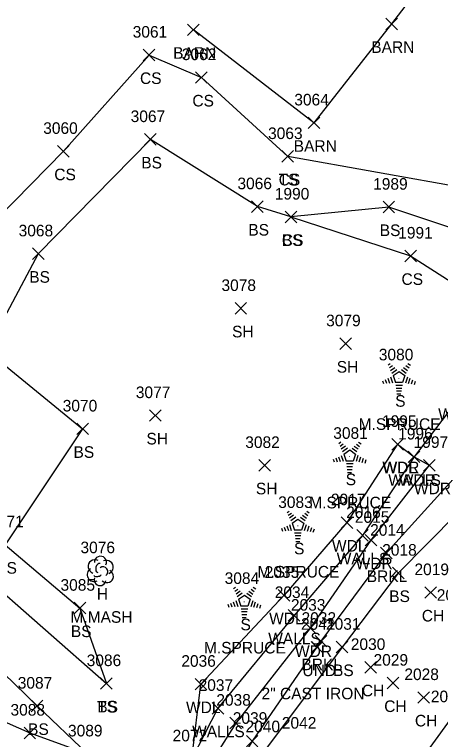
# Model space of a CAD drawing. Extents: x 1499292 to 1501024, y 534584 to 538043.
# Drawn here: x 1499814.4 to 1499887.8, y 537733.8 to 537858.9 of the extents above; entities that cross this region are included whole.
import ezdxf

# ---------------------------------------------------------------- set-up
doc = ezdxf.new("R2010")
doc.units = 0
for name, color, linetype in [('D_A', 7, 'Continuous'), ('D_C', 7, 'Continuous'), ('D_I', 7, 'Continuous'), ('D_TIC', 7, 'Continuous'), ('L_A', 7, 'Continuous'), ('L_C', 7, 'Continuous'), ('L_I', 7, 'Continuous'), ('L_TIC', 7, 'Continuous'), ('LAPB', 7, 'Continuous'), ('LAWA', 7, 'Continuous'), ('LAWE', 7, 'Continuous'), ('LBC', 7, 'Continuous'), ('LELB', 7, 'Continuous'), ('LTC', 7, 'Continuous'), ('LTD', 7, 'Continuous'), ('LWS', 7, 'Continuous')]:
    doc.layers.add(name, color=color, linetype=linetype)

msp = doc.modelspace()

# ---------------------------------------------------------------- linework, layer by layer
at = {"layer": 'D_TIC'}
for points in [[(1499865.55, 537748.77), (1499867.55, 537750.77)], [(1499867.55, 537748.77), (1499865.55, 537750.77)]]:
    msp.add_lwpolyline(points, dxfattribs=at)
at = {"layer": 'L_TIC'}
for points in [[(1499878.39, 537856.32), (1499880.39, 537858.32)], [(1499880.39, 537856.32), (1499878.39, 537858.32)], [(1499844.24, 537855.3), (1499846.24, 537857.3)], [(1499846.24, 537855.3), (1499844.24, 537857.3)], [(1499836.6, 537850.95), (1499838.6, 537852.95)], [(1499838.6, 537850.95), (1499836.6, 537852.95)], [(1499845.63, 537847.07), (1499847.63, 537849.07)], [(1499847.63, 537847.07), (1499845.63, 537849.07)], [(1499865.02, 537839.25), (1499867.02, 537841.25)], [(1499867.02, 537839.25), (1499865.02, 537841.25)], [(1499836.82, 537836.38), (1499838.82, 537838.38)], [(1499838.82, 537836.38), (1499836.82, 537838.38)], [(1499821.83, 537834.34), (1499823.83, 537836.34)], [(1499823.83, 537834.34), (1499821.83, 537836.34)], [(1499860.5, 537833.45), (1499862.5, 537835.45)], [(1499862.5, 537833.45), (1499860.5, 537835.45)], [(1499860.5, 537833.45), (1499862.5, 537835.45)], [(1499862.5, 537833.45), (1499860.5, 537835.45)], [(1499855.27, 537824.79), (1499857.27, 537826.79)], [(1499857.27, 537824.79), (1499855.27, 537826.79)], [(1499877.92, 537824.71), (1499879.92, 537826.71)], [(1499879.92, 537824.71), (1499877.92, 537826.71)], [(1499861.05, 537823.01), (1499863.05, 537825.01)], [(1499863.05, 537823.01), (1499861.05, 537825.01)], [(1499861.05, 537823.01), (1499863.05, 537825.01)], [(1499863.05, 537823.01), (1499861.05, 537825.01)], [(1499817.51, 537816.66), (1499819.51, 537818.66)], [(1499819.51, 537816.66), (1499817.51, 537818.66)], [(1499881.67, 537816.28), (1499883.67, 537818.28)], [(1499883.67, 537816.28), (1499881.67, 537818.28)], [(1499852.42, 537807.23), (1499854.42, 537809.23)], [(1499854.42, 537807.23), (1499852.42, 537809.23)], [(1499870.47, 537801.14), (1499872.47, 537803.14)], [(1499872.47, 537801.14), (1499870.47, 537803.14)], [(1499837.66, 537788.75), (1499839.66, 537790.75)], [(1499839.66, 537788.75), (1499837.66, 537790.75)], [(1499825.14, 537786.44), (1499827.14, 537788.44)], [(1499827.14, 537786.44), (1499825.14, 537788.44)], [(1499879.44, 537783.78), (1499881.44, 537785.78)], [(1499881.44, 537783.78), (1499879.44, 537785.78)], [(1499879.44, 537783.78), (1499881.44, 537785.78)], [(1499881.44, 537783.78), (1499879.44, 537785.78)], [(1499882.28, 537781.61), (1499884.28, 537783.61)], [(1499884.28, 537781.61), (1499882.28, 537783.61)], [(1499882.28, 537781.61), (1499884.28, 537783.61)], [(1499884.28, 537781.61), (1499882.28, 537783.61)], [(1499856.52, 537780.14), (1499858.52, 537782.14)], [(1499858.52, 537780.14), (1499856.52, 537782.14)], [(1499884.89, 537780.16), (1499886.89, 537782.16)], [(1499886.89, 537780.16), (1499884.89, 537782.16)], [(1499870.7, 537770.26), (1499872.7, 537772.26)], [(1499872.7, 537770.26), (1499870.7, 537772.26)], [(1499873.39, 537768.05), (1499875.39, 537770.05)], [(1499875.39, 537768.05), (1499873.39, 537770.05)], [(1499874.84, 537767.23), (1499876.84, 537769.23)], [(1499876.84, 537767.23), (1499874.84, 537769.23)], [(1499877.48, 537765), (1499879.48, 537767)], [(1499879.48, 537765), (1499877.48, 537767)], [(1499879.55, 537761.56), (1499881.55, 537763.56)], [(1499881.55, 537761.56), (1499879.55, 537763.56)], [(1499859.87, 537757.73), (1499861.87, 537759.73)], [(1499861.87, 537757.73), (1499859.87, 537759.73)], [(1499885.12, 537758.2), (1499887.12, 537760.2)], [(1499887.12, 537758.2), (1499885.12, 537760.2)], [(1499824.68, 537755.51), (1499826.68, 537757.51)], [(1499826.68, 537755.51), (1499824.68, 537757.51)], [(1499861.6, 537754.25), (1499863.6, 537756.25)], [(1499863.6, 537754.25), (1499861.6, 537756.25)], [(1499864.39, 537752.07), (1499866.39, 537754.07)], [(1499866.39, 537752.07), (1499864.39, 537754.07)], [(1499866.22, 537749.8), (1499868.22, 537751.8)], [(1499868.22, 537749.8), (1499866.22, 537751.8)], [(1499869.86, 537748.78), (1499871.86, 537750.78)], [(1499871.86, 537748.78), (1499869.86, 537750.78)], [(1499874.79, 537745.29), (1499876.79, 537747.29)], [(1499876.79, 537745.29), (1499874.79, 537747.29)], [(1499829.24, 537742.5), (1499831.24, 537744.5)], [(1499831.24, 537742.5), (1499829.24, 537744.5)], [(1499829.24, 537742.5), (1499831.24, 537744.5)], [(1499831.24, 537742.5), (1499829.24, 537744.5)], [(1499845.55, 537742.39), (1499847.55, 537744.39)], [(1499847.55, 537742.39), (1499845.55, 537744.39)], [(1499878.64, 537742.58), (1499880.64, 537744.58)], [(1499880.64, 537742.58), (1499878.64, 537744.58)], [(1499883.94, 537740.09), (1499885.94, 537742.09)], [(1499885.94, 537740.09), (1499883.94, 537742.09)], [(1499817.31, 537738.62), (1499819.31, 537740.62)], [(1499819.31, 537738.62), (1499817.31, 537740.62)], [(1499848.48, 537738.23), (1499850.48, 537740.23)], [(1499850.48, 537738.23), (1499848.48, 537740.23)], [(1499851.53, 537735.67), (1499853.53, 537737.67)], [(1499853.53, 537735.67), (1499851.53, 537737.67)], [(1499816.05, 537733.96), (1499818.05, 537735.96)], [(1499818.05, 537733.96), (1499816.05, 537735.96)], [(1499854.37, 537732.55), (1499856.37, 537734.55)], [(1499856.37, 537732.55), (1499854.37, 537734.55)]]:
    msp.add_lwpolyline(points, dxfattribs=at)
at = {"layer": 'LAPB'}
msp.add_lwpolyline([(1499801.41, 537738.15), (1499803.85, 537740.8), (1499817.05, 537734.96), (1499826.98, 537731.37), (1499832.07, 537725.79), (1499830.07, 537721.19), (1499824.29, 537718.43), (1499822.44, 537716.53)], dxfattribs=at)
at = {"layer": 'LAWA'}
for points in [[(1499880.44, 537784.78), (1499883.28, 537782.61), (1499885.89, 537781.16), (1499875.84, 537768.23), (1499865.39, 537753.07), (1499852.53, 537736.67), (1499844.57, 537724.02), (1499844.99, 537730.52)], [(1499880.44, 537784.78), (1499871.7, 537771.26), (1499860.87, 537758.73), (1499846.55, 537743.39)], [(1499844.99, 537730.52), (1499846.55, 537743.39)]]:
    msp.add_lwpolyline(points, dxfattribs=at)
at = {"layer": 'LAWE'}
msp.add_lwpolyline([(1499929.73, 537843.16), (1499921.15, 537828.37), (1499911.21, 537810.95), (1499902.71, 537799.07), (1499891.7, 537780.61), (1499878.48, 537766), (1499867.22, 537750.8), (1499855.37, 537733.55), (1499847.56, 537720.49), (1499833.23, 537714.68)], dxfattribs=at)
at = {"layer": 'LBC'}
msp.add_lwpolyline([(1499890.83, 537872.27), (1499879.39, 537857.32), (1499866.02, 537840.25), (1499845.24, 537856.3)], dxfattribs=at)
at = {"layer": 'LELB'}
for points in [[(1499799.26, 537773.33), (1499808.36, 537785), (1499799.96, 537794.9), (1499801.41, 537807.8), (1499808.78, 537821.02), (1499822.83, 537835.34), (1499837.6, 537851.95), (1499846.63, 537848.07), (1499861.5, 537834.45)], [(1499931.33, 537841.3), (1499922.8, 537827.37), (1499912.72, 537807.85), (1499905.96, 537796.12), (1499895.82, 537778.01), (1499880.55, 537762.56), (1499870.86, 537749.78), (1499857.65, 537732.09), (1499849.89, 537720.06), (1499839.9, 537710.15), (1499830.87, 537699.25), (1499819.75, 537691.27), (1499813.25, 537682.44), (1499807.24, 537678.73), (1499801.4, 537680.95), (1499789.92, 537664.22), (1499779.13, 537655.09), (1499771.86, 537652.25), (1499758.58, 537645.46), (1499745.45, 537639.29), (1499734.4, 537633.25), (1499715.96, 537632.7), (1499700.46, 537632.22)], [(1499911.08, 537815.73), (1499889.77, 537822.06), (1499878.92, 537825.71), (1499862.05, 537824.01), (1499856.27, 537825.79), (1499837.82, 537837.38), (1499818.51, 537817.66), (1499809.61, 537800.99), (1499826.14, 537787.44), (1499812.81, 537767.45), (1499825.68, 537756.51), (1499830.24, 537743.5)], [(1499908.06, 537822.08), (1499892.45, 537828.9), (1499861.5, 537834.45)], [(1499862.05, 537824.01), (1499882.67, 537817.28), (1499898.74, 537807.01)], [(1499958.72, 537820.12), (1499949.1, 537803.7), (1499937.21, 537786.88), (1499926.5, 537779.14), (1499915.43, 537766.61), (1499901.39, 537746.71), (1499889.51, 537737.27), (1499877.77, 537721.1), (1499874.08, 537712.66), (1499871.12, 537712.1), (1499865.76, 537707.44), (1499861.54, 537702.35), (1499859.64, 537699.06)], [(1499799.26, 537773.33), (1499808.24, 537762.8), (1499830.24, 537743.5)], [(1499782.83, 537767.39), (1499804.79, 537752.68), (1499818.31, 537739.62), (1499826.98, 537731.37)]]:
    msp.add_lwpolyline(points, dxfattribs=at)
at = {"layer": 'LTC'}
for p, q in [((1499878.82, 537798.47), (1499879.18, 537798.73)), ((1499879.03, 537798.01), (1499879.56, 537798.39)), ((1499881.85, 537798.36), (1499882.4, 537797.97)), ((1499882.22, 537798.71), (1499882.64, 537798.41)), ((1499879.24, 537797.54), (1499879.95, 537798.05)), ((1499879.45, 537797.08), (1499880.33, 537797.71)), ((1499879.68, 537796.62), (1499880.69, 537797.36)), ((1499880.69, 537797.36), (1499881.69, 537796.63)), ((1499881.11, 537797.67), (1499881.92, 537797.08)), ((1499881.48, 537798.02), (1499882.16, 537797.52)), ((1499877.86, 537795.75), (1499878.01, 537795.28)), ((1499878.31, 537795.97), (1499878.52, 537795.32)), ((1499878.77, 537796.19), (1499879.04, 537795.35)), ((1499879.22, 537796.4), (1499879.55, 537795.38)), ((1499879.68, 537796.62), (1499880.07, 537795.43)), ((1499881.69, 537796.63), (1499881.3, 537795.43)), ((1499882.12, 537796.36), (1499881.79, 537795.32)), ((1499882.57, 537796.11), (1499882.28, 537795.22)), ((1499883.01, 537795.86), (1499882.78, 537795.13)), ((1499881.3, 537795.43), (1499880.07, 537795.43)), ((1499881.26, 537794.93), (1499880.11, 537794.93)), ((1499881.17, 537794.43), (1499880.19, 537794.43)), ((1499883.46, 537795.61), (1499883.27, 537795.03)), ((1499881.09, 537793.93), (1499880.26, 537793.93)), ((1499881.01, 537793.43), (1499880.33, 537793.43)), ((1499870.31, 537784.93), (1499870.67, 537785.19)), ((1499870.52, 537784.46), (1499871.05, 537784.85)), ((1499870.73, 537784), (1499871.44, 537784.51)), ((1499872.97, 537784.47), (1499873.65, 537783.98)), ((1499873.34, 537784.82), (1499873.89, 537784.42)), ((1499873.71, 537785.17), (1499874.13, 537784.87)), ((1499870.94, 537783.53), (1499871.82, 537784.17)), ((1499871.17, 537783.08), (1499872.18, 537783.81)), ((1499872.18, 537783.81), (1499873.18, 537783.09)), ((1499872.6, 537784.12), (1499873.41, 537783.54)), ((1499869.35, 537782.21), (1499869.5, 537781.74)), ((1499869.8, 537782.43), (1499870.01, 537781.77)), ((1499870.26, 537782.64), (1499870.53, 537781.81)), ((1499870.71, 537782.86), (1499871.04, 537781.84)), ((1499871.17, 537783.08), (1499871.55, 537781.88)), ((1499872.78, 537781.88), (1499871.55, 537781.88)), ((1499873.18, 537783.09), (1499872.78, 537781.88)), ((1499873.61, 537782.82), (1499873.28, 537781.78)), ((1499874.06, 537782.57), (1499873.77, 537781.68)), ((1499874.5, 537782.32), (1499874.27, 537781.59)), ((1499874.95, 537782.07), (1499874.76, 537781.49)), ((1499872.75, 537781.38), (1499871.6, 537781.38)), ((1499872.66, 537780.88), (1499871.67, 537780.88)), ((1499872.58, 537780.38), (1499871.75, 537780.38)), ((1499872.5, 537779.88), (1499871.82, 537779.88)), ((1499861.4, 537773), (1499861.75, 537773.26)), ((1499864.79, 537773.24), (1499865.21, 537772.94)), ((1499861.6, 537772.54), (1499862.13, 537772.92)), ((1499861.81, 537772.07), (1499862.52, 537772.58)), ((1499862.02, 537771.6), (1499862.9, 537772.24)), ((1499862.25, 537771.15), (1499863.26, 537771.88)), ((1499863.26, 537771.88), (1499864.26, 537771.16)), ((1499863.68, 537772.2), (1499864.49, 537771.61)), ((1499864.05, 537772.55), (1499864.73, 537772.05)), ((1499864.42, 537772.89), (1499864.97, 537772.49)), ((1499861.34, 537770.71), (1499861.61, 537769.88)), ((1499861.79, 537770.93), (1499862.12, 537769.91)), ((1499862.25, 537771.15), (1499862.64, 537769.96)), ((1499864.26, 537771.16), (1499863.87, 537769.96)), ((1499864.69, 537770.89), (1499864.36, 537769.85)), ((1499865.14, 537770.64), (1499864.85, 537769.75)), ((1499860.43, 537770.28), (1499860.58, 537769.81)), ((1499860.88, 537770.5), (1499861.09, 537769.85)), ((1499863.87, 537769.96), (1499862.64, 537769.96)), ((1499863.83, 537769.46), (1499862.68, 537769.46)), ((1499865.58, 537770.39), (1499865.35, 537769.66)), ((1499866.03, 537770.14), (1499865.84, 537769.56)), ((1499863.74, 537768.96), (1499862.76, 537768.96)), ((1499863.66, 537768.46), (1499862.83, 537768.46)), ((1499863.58, 537767.96), (1499862.9, 537767.96)), ((1499852.17, 537759.89), (1499852.52, 537760.14)), ((1499852.38, 537759.42), (1499852.91, 537759.8)), ((1499852.59, 537758.95), (1499853.29, 537759.47)), ((1499854.82, 537759.43), (1499855.5, 537758.94)), ((1499855.19, 537759.78), (1499855.74, 537759.38)), ((1499855.56, 537760.13), (1499855.98, 537759.82)), ((1499852.8, 537758.49), (1499853.67, 537759.13)), ((1499853.02, 537758.03), (1499854.03, 537758.77)), ((1499854.03, 537758.77), (1499855.03, 537758.04)), ((1499854.45, 537759.08), (1499855.26, 537758.49)), ((1499851.2, 537757.17), (1499851.35, 537756.7)), ((1499851.65, 537757.38), (1499851.87, 537756.73)), ((1499852.11, 537757.6), (1499852.38, 537756.76)), ((1499852.57, 537757.81), (1499852.9, 537756.8)), ((1499853.02, 537758.03), (1499853.41, 537756.84)), ((1499855.03, 537758.04), (1499854.64, 537756.84)), ((1499855.47, 537757.77), (1499855.13, 537756.73)), ((1499855.91, 537757.52), (1499855.62, 537756.64)), ((1499856.36, 537757.27), (1499856.12, 537756.54)), ((1499856.8, 537757.02), (1499856.61, 537756.45)), ((1499854.64, 537756.84), (1499853.41, 537756.84)), ((1499854.6, 537756.34), (1499853.45, 537756.34)), ((1499854.52, 537755.84), (1499853.53, 537755.84)), ((1499854.43, 537755.34), (1499853.6, 537755.34)), ((1499854.35, 537754.84), (1499853.67, 537754.84))]:
    msp.add_line(p, q, dxfattribs=at)
at = {"layer": 'LTD'}
msp.add_line((1499829.17, 537762.98), (1499829.17, 537762.98), dxfattribs=at)
msp.add_line((1499829.17, 537762.98), (1499829.17, 537762.98), dxfattribs=at)
msp.add_arc((1499829.22, 537764.41), 1.05, 335.5272, 180.9563, dxfattribs=at)
for centre, major_axis, ratio, start_param, end_param in [((1499828.38, 537763.64), (1.21, -0.51), 0.895232, 1.570796, 4.712389), ((1499830.21, 537763.56), (-1.14, -0.48), 0.949671, 1.570796, 4.712389), ((1499828.09, 537762.27), (0.58, -1.04), 0.959034, 3.141593, 6.283185), ((1499828.96, 537763.43), (-0.208, -0.792), 0.645439, 3.141593, 6.283185), ((1499829.67, 537762.81), (-0.5, 0.667), 0.989748, 3.141593, 6.283185), ((1499828.71, 537762.23), (-0.625, -0.083), 0.423636, 0, 3.141593), ((1499830.17, 537762.14), (-1.09, 0.79), 0.841452, 1.570796, 4.712389), ((1499829.17, 537761.48), (0.26, 1.06), 0.942809, 1.570796, 4.712389)]:
    msp.add_ellipse(centre, major_axis=major_axis, ratio=ratio, start_param=start_param, end_param=end_param, dxfattribs=at)
at = {"layer": 'LWS'}
msp.add_lwpolyline([(1499897.8, 537803.79), (1499891.88, 537793.96), (1499883.28, 537782.61), (1499874.39, 537769.05), (1499862.6, 537755.25), (1499849.48, 537739.23), (1499844.99, 537730.52)], dxfattribs=at)

# ---------------------------------------------------------------- texts
at = {"layer": 'D_A'}
msp.add_text('UND', height=2, dxfattribs=at).set_placement((1499864.03, 537744.77))
at = {"layer": 'D_C'}
msp.add_text('2" CAST IRON', height=2, dxfattribs=at).set_placement((1499856.99, 537740.77))
at = {"layer": 'D_I'}
msp.add_text('2041', height=2, dxfattribs=at).set_placement((1499863.78, 537752.77))
at = {"layer": 'L_A'}
for s, p in [('BARN', (1499841.75, 537851.3)), ('BARN', (1499875.9, 537852.32)), ('CS', (1499836.04, 537846.95)), ('CS', (1499845.07, 537843.07)), ('BARN', (1499862.53, 537835.25)), ('BS', (1499836.26, 537832.38)), ('CS', (1499821.27, 537830.34)), ('TS', (1499859.91, 537829.45)), ('CS', (1499859.94, 537829.45)), ('BS', (1499854.71, 537820.79)), ('BS', (1499877.36, 537820.71)), ('CS', (1499860.49, 537819.01)), ('BS', (1499860.49, 537819.01)), ('BS', (1499816.95, 537812.66)), ('CS', (1499881.11, 537812.28)), ('SH', (1499851.91, 537803.23)), ('SH', (1499869.95, 537797.14)), ('S', (1499880.02, 537791.26)), ('WALLS', (1499887.43, 537788.96)), ('SH', (1499837.15, 537784.75)), ('BS', (1499824.58, 537782.44)), ('WDR', (1499877.8, 537779.78)), ('WDL', (1499877.86, 537779.78)), ('S', (1499871.5, 537777.72)), ('WALLS', (1499878.83, 537777.61)), ('WDR', (1499880.64, 537777.61)), ('SH', (1499856.01, 537776.14)), ('WDR', (1499883.25, 537776.16)), ('WDL', (1499869.12, 537766.26)), ('S', (1499862.59, 537765.79)), ('WALLS', (1499869.94, 537764.05)), ('BS', (1499811.26, 537762.45)), ('WDR', (1499873.2, 537763.23)), ('BRKL', (1499875.12, 537761)), ('H', (1499828.6, 537757.98)), ('BS', (1499878.99, 537757.56)), ('WDL', (1499858.29, 537753.73)), ('CH', (1499884.61, 537754.2)), ('S', (1499853.36, 537752.68)), ('BS', (1499824.12, 537751.51)), ('WALLS', (1499858.14, 537750.25)), ('WDR', (1499862.75, 537748.07)), ('BRKL', (1499863.87, 537745.8)), ('BS', (1499869.3, 537744.78)), ('CH', (1499874.28, 537741.29)), ('CH', (1499878.13, 537738.58)), ('TS', (1499828.65, 537738.5)), ('BS', (1499828.68, 537738.5)), ('WDL', (1499843.97, 537738.39)), ('CH', (1499883.42, 537736.09)), ('BS', (1499816.75, 537734.62)), ('WALLS', (1499845.02, 537734.23))]:
    msp.add_text(s, height=2, dxfattribs=at).set_placement(p)
at = {"layer": 'L_C'}
for s, p in [('M.SPRUCE', (1499873.72, 537787.26)), ('M.SPRUCE', (1499865.21, 537773.72)), ('M.SPRUCE', (1499856.29, 537761.79)), ('M.MASH', (1499824.05, 537753.98)), ('M.SPRUCE', (1499847.06, 537748.68))]:
    msp.add_text(s, height=2, dxfattribs=at).set_placement(p)
at = {"layer": 'L_I'}
for s, p in [('3061', (1499834.78, 537854.95)), ('3062', (1499843.24, 537851.07)), ('3064', (1499862.63, 537843.25)), ('3067', (1499834.43, 537840.38)), ('3060', (1499819.36, 537838.34)), ('3063', (1499858.11, 537837.45)), ('3063', (1499858.11, 537837.45)), ('3066', (1499852.83, 537828.79)), ('1989', (1499876.22, 537828.71)), ('1990', (1499859.27, 537827.01)), ('1990', (1499859.27, 537827.01)), ('3068', (1499815.12, 537820.66)), ('1991', (1499880.54, 537820.28)), ('3078', (1499850.08, 537811.23)), ('3079', (1499868.12, 537805.14)), ('3080', (1499877.2, 537799.26)), ('3077', (1499835.32, 537792.75)), ('3070', (1499822.72, 537790.44)), ('1995', (1499877.75, 537787.78)), ('1995', (1499877.75, 537787.78)), ('3081', (1499869.35, 537785.72)), ('1996', (1499880.53, 537785.61)), ('1996', (1499880.53, 537785.61)), ('3082', (1499854.18, 537784.14)), ('1997', (1499883.2, 537784.16)), ('3083', (1499859.86, 537773.79)), ('2017', (1499868.93, 537774.26)), ('2016', (1499871.57, 537772.05)), ('2015', (1499873.07, 537771.23)), ('3071', (1499810.04, 537770.45)), ('2014', (1499875.7, 537769)), ('3076', (1499825.78, 537765.98)), ('2018', (1499877.78, 537765.56)), ('2035', (1499857.53, 537761.73)), ('2019', (1499883.34, 537762.2)), ('3084', (1499850.63, 537760.68)), ('3085', (1499822.34, 537759.51)), ('2034', (1499859.26, 537758.25)), ('2020', (1499887.19, 537757.77)), ('2033', (1499862.05, 537756.07)), ('2032', (1499863.88, 537753.8)), ('2031', (1499868.09, 537752.78)), ('2030', (1499872.37, 537749.29)), ('3086', (1499826.85, 537746.5)), ('3086', (1499826.85, 537746.5)), ('2036', (1499843.16, 537746.39)), ('2029', (1499876.29, 537746.58)), ('2028', (1499881.6, 537744.09)), ('3087', (1499814.97, 537742.62)), ('2037', (1499846.14, 537742.23)), ('2027', (1499886.17, 537740.27)), ('2038', (1499849.19, 537739.67)), ('3088', (1499813.72, 537737.96)), ('2039', (1499852.03, 537736.55)), ('2040', (1499854.23, 537735.09)), ('2042', (1499860.49, 537735.71)), ('3089', (1499823.63, 537734.37)), ('3089', (1499823.63, 537734.37)), ('2072', (1499841.66, 537733.52)), ('2072', (1499841.66, 537733.52)), ('2072', (1499841.66, 537733.52))]:
    msp.add_text(s, height=2, dxfattribs=at).set_placement(p)
at = {"layer": 'LTC'}
for p in [(1499880.57, 537796.37), (1499872.06, 537782.83), (1499863.14, 537770.9), (1499853.91, 537757.78)]:
    msp.add_text('.', height=1.04, rotation=270, dxfattribs=at).set_placement(p)

doc.saveas('drawing.dxf')
